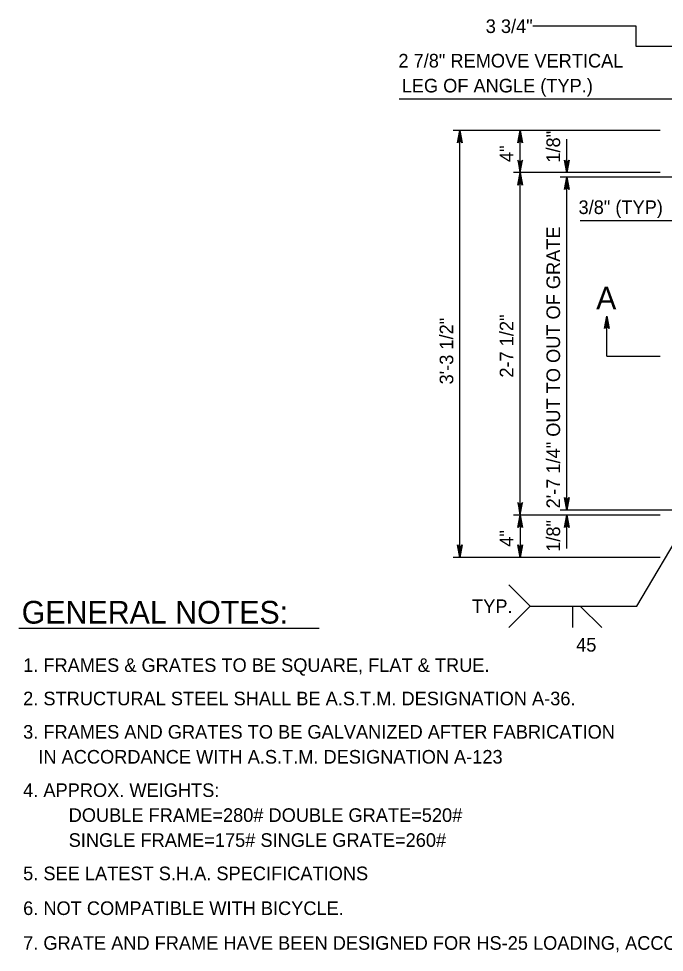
# Model space of a CAD drawing. Extents: x 0.7 to 7.67, y -7.49 to 2.47.
# Drawn here: x 0.697 to 3.543, y -5.992 to -1.876 of the extents above; entities that cross this region are included whole.
import ezdxf

# ---------------------------------------------------------------- set-up
doc = ezdxf.new("R2010")
doc.units = 0
for name, color, linetype in [('DETL-DIMS', 7, 'Continuous'), ('DETL-NOTE', 7, 'Continuous'), ('DETL-TITL', 7, 'Continuous')]:
    doc.layers.add(name, color=color, linetype=linetype)

msp = doc.modelspace()

# ---------------------------------------------------------------- linework, layer by layer
at = {"layer": 'DETL-DIMS'}
for p, q in [((3.419, -1.9094), (2.9626, -1.9094)), ((3.419, -1.9994), (3.419, -1.9094)), ((3.6422, -1.9994), (3.419, -1.9994)), ((3.6194, -2.2309), (2.374, -2.2309)), ((3.5246, -2.3688), (2.6128, -2.3688)), ((2.6422, -4.2511), (2.6422, -2.3688)), ((2.9069, -2.5551), (2.9069, -2.3688)), ((3.1128, -2.5551), (3.1128, -2.408)), ((3.5246, -2.5551), (2.8775, -2.5551)), ((2.9069, -4.0649), (2.9069, -2.5551)), ((3.7349, -2.5748), (3.0834, -2.5748)), ((3.1128, -4.0425), (3.1128, -2.5748)), ((3.6863, -2.767), (3.1719, -2.767)), ((3.2893, -3.3641), (3.2893, -3.1877)), ((3.2893, -3.3641), (3.5246, -3.3641)), ((3.5246, -4.0649), (2.8775, -4.0649)), ((2.9069, -4.0649), (2.9069, -4.2511)), ((3.7362, -4.0425), (3.0834, -4.0425)), ((3.1128, -4.2119), (3.1128, -4.0649)), ((3.4216, -4.4666), (3.6583, -4.0653)), ((3.5246, -4.2511), (2.6128, -4.2511)), ((2.951, -4.4666), (3.2333, -4.4666)), ((3.1392, -4.5607), (3.1392, -4.4666)), ((3.1392, -4.4666), (3.185, -4.4666)), ((3.1726, -4.4666), (3.2668, -4.5607)), ((3.2333, -4.4666), (3.4216, -4.4666))]:
    msp.add_line(p, q, dxfattribs=at)
for points in [[(2.6422, -2.3688), (2.6525, -2.4236), (2.6496, -2.4194), (2.6459, -2.4172), (2.6422, -2.4166), (2.6385, -2.4172), (2.6349, -2.4194), (2.6319, -2.4236), (2.6422, -2.3688), (2.6349, -2.4194), (2.6385, -2.4172), (2.6422, -2.3688), (2.6422, -2.4166), (2.6459, -2.4172), (2.6422, -2.3688), (2.6496, -2.4194)], [(2.9069, -2.3688), (2.9172, -2.4236), (2.9143, -2.4194), (2.9106, -2.4172), (2.9069, -2.4166), (2.9032, -2.4172), (2.8996, -2.4194), (2.8966, -2.4236), (2.9069, -2.3688), (2.8996, -2.4194), (2.9032, -2.4172), (2.9069, -2.3688), (2.9069, -2.4166), (2.9106, -2.4172), (2.9069, -2.3688), (2.9143, -2.4194)], [(2.9069, -2.5551), (2.9172, -2.5002), (2.9143, -2.5045), (2.9106, -2.5066), (2.9069, -2.5073), (2.9032, -2.5066), (2.8996, -2.5045), (2.8966, -2.5002), (2.9069, -2.5551), (2.8996, -2.5045), (2.9032, -2.5066), (2.9069, -2.5551), (2.9069, -2.5073), (2.9106, -2.5066), (2.9069, -2.5551), (2.9143, -2.5045)], [(3.1128, -2.5551), (3.1025, -2.5002), (3.1054, -2.5045), (3.1091, -2.5066), (3.1128, -2.5073), (3.1165, -2.5066), (3.1202, -2.5045), (3.1231, -2.5002), (3.1128, -2.5551), (3.1202, -2.5045), (3.1165, -2.5066), (3.1128, -2.5551), (3.1128, -2.5073), (3.1091, -2.5066), (3.1128, -2.5551), (3.1054, -2.5045)], [(2.9069, -2.5551), (2.9172, -2.6099), (2.9143, -2.6057), (2.9106, -2.6035), (2.9069, -2.6029), (2.9032, -2.6035), (2.8996, -2.6057), (2.8966, -2.6099), (2.9069, -2.5551), (2.8996, -2.6057), (2.9032, -2.6035), (2.9069, -2.5551), (2.9069, -2.6029), (2.9106, -2.6035), (2.9069, -2.5551), (2.9143, -2.6057)], [(3.1128, -2.5748), (3.1231, -2.6296), (3.1202, -2.6254), (3.1165, -2.6232), (3.1128, -2.6226), (3.1091, -2.6232), (3.1054, -2.6254), (3.1025, -2.6296), (3.1128, -2.5748), (3.1054, -2.6254), (3.1091, -2.6232), (3.1128, -2.5748), (3.1128, -2.6226), (3.1165, -2.6232), (3.1128, -2.5748), (3.1202, -2.6254)], [(3.2893, -3.1877), (3.2996, -3.2425), (3.2966, -3.2383), (3.2929, -3.2361), (3.2893, -3.2355), (3.2856, -3.2361), (3.2819, -3.2383), (3.279, -3.2425), (3.2893, -3.1877), (3.2819, -3.2383), (3.2856, -3.2361), (3.2893, -3.1877), (3.2893, -3.2355), (3.2929, -3.2361), (3.2893, -3.1877), (3.2966, -3.2383)], [(3.1128, -4.0425), (3.1025, -3.9877), (3.1054, -3.9919), (3.1091, -3.9941), (3.1128, -3.9947), (3.1165, -3.9941), (3.1202, -3.9919), (3.1231, -3.9877), (3.1128, -4.0425), (3.1202, -3.9919), (3.1165, -3.9941), (3.1128, -4.0425), (3.1128, -3.9947), (3.1091, -3.9941), (3.1128, -4.0425), (3.1054, -3.9919)], [(2.9069, -4.0649), (2.9172, -4.01), (2.9143, -4.0143), (2.9106, -4.0164), (2.9069, -4.0171), (2.9032, -4.0164), (2.8996, -4.0143), (2.8966, -4.01), (2.9069, -4.0649), (2.8996, -4.0143), (2.9032, -4.0164), (2.9069, -4.0649), (2.9069, -4.0171), (2.9106, -4.0164), (2.9069, -4.0649), (2.9143, -4.0143)], [(2.9069, -4.0649), (2.9172, -4.1197), (2.9143, -4.1155), (2.9106, -4.1133), (2.9069, -4.1127), (2.9032, -4.1133), (2.8996, -4.1155), (2.8966, -4.1197), (2.9069, -4.0649), (2.8996, -4.1155), (2.9032, -4.1133), (2.9069, -4.0649), (2.9069, -4.1127), (2.9106, -4.1133), (2.9069, -4.0649), (2.9143, -4.1155)], [(3.1128, -4.0649), (3.1231, -4.1197), (3.1202, -4.1155), (3.1165, -4.1133), (3.1128, -4.1127), (3.1091, -4.1133), (3.1054, -4.1155), (3.1025, -4.1197), (3.1128, -4.0649), (3.1054, -4.1155), (3.1091, -4.1133), (3.1128, -4.0649), (3.1128, -4.1127), (3.1165, -4.1133), (3.1128, -4.0649), (3.1202, -4.1155)], [(2.6422, -4.2511), (2.6319, -4.1963), (2.6349, -4.2005), (2.6385, -4.2027), (2.6422, -4.2034), (2.6459, -4.2027), (2.6496, -4.2005), (2.6525, -4.1963), (2.6422, -4.2511), (2.6496, -4.2005), (2.6459, -4.2027), (2.6422, -4.2511), (2.6422, -4.2034), (2.6385, -4.2027), (2.6422, -4.2511), (2.6349, -4.2005)], [(2.9069, -4.2511), (2.8966, -4.1963), (2.8996, -4.2005), (2.9032, -4.2027), (2.9069, -4.2034), (2.9106, -4.2027), (2.9143, -4.2005), (2.9172, -4.1963), (2.9069, -4.2511), (2.9143, -4.2005), (2.9106, -4.2027), (2.9069, -4.2511), (2.9069, -4.2034), (2.9032, -4.2027), (2.9069, -4.2511), (2.8996, -4.2005)], [(2.8568, -4.3725), (2.951, -4.4666), (2.8568, -4.5607)]]:
    msp.add_lwpolyline(points, dxfattribs=at)
at = {"layer": 'DETL-NOTE'}
msp.add_line((0.6974, -4.5636), (2.0223, -4.5636), dxfattribs=at)

# ---------------------------------------------------------------- texts
for s, height, p in [('3 3/4"', 0.06, (2.7557, -1.9394)), ('2 7/8" REMOVE VERTICAL', 0.06, (2.3708, -2.0915)), ('LEG OF ANGLE (TYP.)', 0.06, (2.3853, -2.2015)), ('3/8" (TYP)', 0.06, (3.1647, -2.7375)), ('GENERAL NOTES:', 0.1, (0.7108, -4.5432)), ('TYP.', 0.06, (2.6956, -4.4966)), ('45', 0.06, (3.154, -4.6665)), ('1. FRAMES & GRATES TO BE SQUARE, FLAT & TRUE.', 0.06, (0.7171, -4.7563)), ('2. STRUCTURAL STEEL SHALL BE A.S.T.M. DESIGNATION A-36.', 0.06, (0.7171, -4.9034)), ('3. FRAMES AND GRATES TO BE GALVANIZED AFTER FABRICATION', 0.06, (0.7171, -5.0504)), ('   IN ACCORDANCE WITH A.S.T.M. DESIGNATION A-123', 0.06, (0.7171, -5.1604)), ('4. APPROX. WEIGHTS:', 0.06, (0.7171, -5.3075)), ('         DOUBLE FRAME=280# DOUBLE GRATE=520#', 0.06, (0.7171, -5.4175)), ('         SINGLE FRAME=175# SINGLE GRATE=260#', 0.06, (0.7171, -5.5275)), ('5. SEE LATEST S.H.A. SPECIFICATIONS  ', 0.06, (0.7171, -5.6745)), ('6. NOT COMPATIBLE WITH BICYCLE. ', 0.06, (0.7171, -5.8279)), ('7. GRATE AND FRAME HAVE BEEN DESIGNED FOR HS-25 LOADING, ACCORDING TO AASHTO LRFD BRIDGE DESIGN SPECIFICATIONS. ', 0.06, (0.7171, -5.9813))]:
    msp.add_text(s, height=height, dxfattribs=at).set_placement(p)
for s, p in [('1/8"', (3.0834, -2.5109)), ('4"', (2.8775, -2.5083)), ('2\'-7 1/4" OUT TO OUT OF GRATE', (3.0834, -4.0353)), ('3\'-3 1/2"', (2.6128, -3.4887)), ('2-7 1/2"', (2.8775, -3.4587)), ('1/8"', (3.0834, -4.2266)), ('4"', (2.8775, -4.2043))]:
    msp.add_text(s, height=0.06, rotation=90, dxfattribs=at).set_placement(p)
at = {"layer": 'DETL-TITL'}
msp.add_text('A', height=0.1, dxfattribs=at).set_placement((3.2423, -3.1582))

doc.saveas('drawing.dxf')
